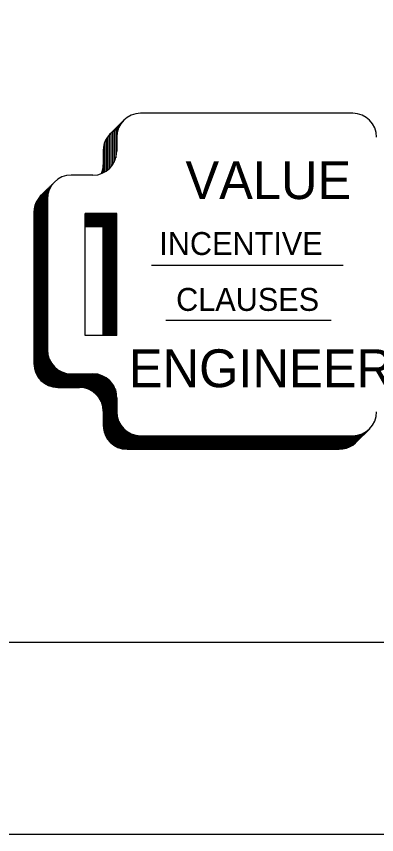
# Model space of a CAD drawing. Extents: x 22369.62 to 22373.29, y 22369.62 to 22372.46.
# Drawn here: x 22369.7905 to 22369.8691, y 22369.6213 to 22369.7998 of the extents above; entities that cross this region are included whole.
import ezdxf

# ---------------------------------------------------------------- set-up
doc = ezdxf.new("R2010")
doc.units = 0
for name, color, linetype in [('Level 1', 7, 'Continuous'), ('Level 2', 7, 'Continuous'), ('Level 7', 7, 'Continuous'), ('Level 9', 7, 'Continuous')]:
    doc.layers.add(name, color=color, linetype=linetype)

msp = doc.modelspace()

# ---------------------------------------------------------------- linework, layer by layer
at = {"layer": 'Level 1'}
msp.add_lwpolyline([(22369.6213, 22372.4553), (22373.288, 22372.4553), (22373.288, 22369.6213), (22369.6213, 22369.6213)], close=True, dxfattribs=at)
at = {"layer": 'Level 2'}
for p, q in [((22369.81094, 22369.77414), (22369.81388, 22369.77709)), ((22369.81261, 22369.775), (22369.81261, 22369.77582)), ((22369.81288, 22369.77568), (22369.81288, 22369.77609)), ((22369.81314, 22369.77614), (22369.81314, 22369.77635)), ((22369.81336, 22369.77648), (22369.81336, 22369.77657)), ((22369.81073, 22369.77391), (22369.81073, 22369.76654)), ((22369.81107, 22369.77428), (22369.81107, 22369.76689)), ((22369.81143, 22369.77463), (22369.81143, 22369.76735)), ((22369.8118, 22369.77501), (22369.8118, 22369.76798)), ((22369.81215, 22369.77536), (22369.81215, 22369.76887)), ((22369.81236, 22369.7734), (22369.81236, 22369.77557)), ((22369.8097, 22369.77214), (22369.8097, 22369.76579)), ((22369.81005, 22369.77295), (22369.81005, 22369.766)), ((22369.81037, 22369.77347), (22369.81037, 22369.76624)), ((22369.80941, 22369.77046), (22369.80941, 22369.76564)), ((22369.79581, 22369.76065), (22369.79876, 22369.7636)), ((22369.79661, 22369.76146), (22369.79661, 22369.71972)), ((22369.79676, 22369.7616), (22369.79676, 22369.71962)), ((22369.79689, 22369.76174), (22369.79689, 22369.71954)), ((22369.79703, 22369.76187), (22369.79703, 22369.71947)), ((22369.79712, 22369.76197), (22369.79712, 22369.71941)), ((22369.79724, 22369.75991), (22369.79724, 22369.76208)), ((22369.79735, 22369.761), (22369.79735, 22369.7622)), ((22369.7975, 22369.76154), (22369.7975, 22369.76234)), ((22369.79761, 22369.76185), (22369.79761, 22369.76246)), ((22369.79772, 22369.76209), (22369.79772, 22369.76256)), ((22369.79781, 22369.76229), (22369.79781, 22369.76265)), ((22369.79791, 22369.76249), (22369.79791, 22369.76276)), ((22369.79802, 22369.76265), (22369.79802, 22369.76286)), ((22369.79812, 22369.76282), (22369.79812, 22369.76297)), ((22369.79823, 22369.76297), (22369.79823, 22369.76307)), ((22369.79506, 22369.7597), (22369.79506, 22369.72132)), ((22369.79523, 22369.75995), (22369.79523, 22369.72107)), ((22369.7954, 22369.76019), (22369.7954, 22369.72083)), ((22369.79555, 22369.76036), (22369.79555, 22369.72065)), ((22369.79569, 22369.76052), (22369.79569, 22369.7205)), ((22369.79583, 22369.76066), (22369.79583, 22369.72035)), ((22369.79601, 22369.76085), (22369.79601, 22369.72019)), ((22369.79613, 22369.76098), (22369.79613, 22369.72007)), ((22369.79627, 22369.76111), (22369.79627, 22369.71997)), ((22369.79644, 22369.76128), (22369.79644, 22369.71984)), ((22369.79444, 22369.75819), (22369.79444, 22369.72283)), ((22369.79459, 22369.75872), (22369.79459, 22369.7223)), ((22369.79476, 22369.75912), (22369.79476, 22369.72189)), ((22369.79489, 22369.7594), (22369.79489, 22369.72161)), ((22369.79429, 22369.75697), (22369.79429, 22369.72405)), ((22369.81236, 22369.75665), (22369.80547, 22369.75665)), ((22369.81236, 22369.75652), (22369.80547, 22369.75652)), ((22369.81236, 22369.75636), (22369.80547, 22369.75636)), ((22369.81236, 22369.75621), (22369.80547, 22369.75621)), ((22369.81236, 22369.75604), (22369.80547, 22369.75604)), ((22369.81236, 22369.75679), (22369.80941, 22369.75384)), ((22369.81236, 22369.75588), (22369.80547, 22369.75588)), ((22369.81236, 22369.75573), (22369.80547, 22369.75573)), ((22369.81236, 22369.75556), (22369.80547, 22369.75556)), ((22369.81236, 22369.75541), (22369.80547, 22369.75541)), ((22369.81236, 22369.75526), (22369.80547, 22369.75526)), ((22369.81236, 22369.7551), (22369.80547, 22369.7551)), ((22369.81236, 22369.75496), (22369.80547, 22369.75496)), ((22369.81236, 22369.75481), (22369.80547, 22369.75481)), ((22369.81236, 22369.75469), (22369.80547, 22369.75469)), ((22369.81236, 22369.75453), (22369.80547, 22369.75453)), ((22369.81236, 22369.7544), (22369.80547, 22369.7544)), ((22369.81236, 22369.75427), (22369.80547, 22369.75427)), ((22369.81236, 22369.75414), (22369.80547, 22369.75414)), ((22369.81236, 22369.75399), (22369.80547, 22369.75399)), ((22369.80941, 22369.75384), (22369.80547, 22369.75384)), ((22369.80941, 22369.73012), (22369.80941, 22369.75384)), ((22369.80956, 22369.73012), (22369.80956, 22369.75399)), ((22369.80968, 22369.73012), (22369.80968, 22369.75399)), ((22369.8098, 22369.73012), (22369.8098, 22369.75399)), ((22369.8099, 22369.73012), (22369.8099, 22369.75399)), ((22369.81006, 22369.73012), (22369.81006, 22369.75399)), ((22369.8102, 22369.73012), (22369.8102, 22369.75399)), ((22369.81034, 22369.73012), (22369.81034, 22369.75399)), ((22369.81045, 22369.73012), (22369.81045, 22369.75399)), ((22369.81061, 22369.73012), (22369.81061, 22369.75399)), ((22369.81075, 22369.73012), (22369.81075, 22369.75399)), ((22369.81086, 22369.73012), (22369.81086, 22369.75399)), ((22369.811, 22369.73012), (22369.811, 22369.75399)), ((22369.81113, 22369.73012), (22369.81113, 22369.75399)), ((22369.81129, 22369.73012), (22369.81129, 22369.75399)), ((22369.81141, 22369.73012), (22369.81141, 22369.75399)), ((22369.81154, 22369.73012), (22369.81154, 22369.75399)), ((22369.8117, 22369.73012), (22369.8117, 22369.75399)), ((22369.81185, 22369.73012), (22369.81185, 22369.75399)), ((22369.81201, 22369.73012), (22369.81201, 22369.75399)), ((22369.81211, 22369.73012), (22369.81211, 22369.75399)), ((22369.81225, 22369.73012), (22369.81225, 22369.75399)), ((22369.79731, 22369.72613), (22369.79731, 22369.71932)), ((22369.79748, 22369.72544), (22369.79748, 22369.71925)), ((22369.79763, 22369.72501), (22369.79763, 22369.71919)), ((22369.79779, 22369.72466), (22369.79779, 22369.71913)), ((22369.79798, 22369.72432), (22369.79798, 22369.71907)), ((22369.79811, 22369.72411), (22369.79811, 22369.71903)), ((22369.79825, 22369.72391), (22369.79825, 22369.719)), ((22369.79843, 22369.72369), (22369.79843, 22369.71896)), ((22369.79857, 22369.72352), (22369.79857, 22369.71893)), ((22369.79873, 22369.72335), (22369.79873, 22369.7189)), ((22369.79888, 22369.7232), (22369.79888, 22369.71887)), ((22369.79904, 22369.72306), (22369.79904, 22369.71886)), ((22369.79919, 22369.72294), (22369.79919, 22369.71885)), ((22369.79936, 22369.7228), (22369.79936, 22369.71884)), ((22369.79952, 22369.72269), (22369.79952, 22369.71884)), ((22369.79968, 22369.72259), (22369.79968, 22369.71884)), ((22369.79983, 22369.7225), (22369.79983, 22369.71884)), ((22369.80002, 22369.72239), (22369.80002, 22369.71884)), ((22369.80015, 22369.72232), (22369.80015, 22369.71884)), ((22369.80024, 22369.72228), (22369.80024, 22369.71884)), ((22369.80037, 22369.72222), (22369.80037, 22369.71884)), ((22369.80051, 22369.72216), (22369.80051, 22369.71884)), ((22369.80068, 22369.7221), (22369.80068, 22369.71884)), ((22369.80084, 22369.72204), (22369.80084, 22369.71884)), ((22369.801, 22369.722), (22369.801, 22369.71884)), ((22369.80121, 22369.72194), (22369.80121, 22369.71884)), ((22369.80139, 22369.72189), (22369.80139, 22369.71884)), ((22369.80155, 22369.72186), (22369.80155, 22369.71884)), ((22369.80166, 22369.72185), (22369.80166, 22369.71884)), ((22369.80182, 22369.72183), (22369.80182, 22369.71884)), ((22369.80196, 22369.72181), (22369.80196, 22369.71884)), ((22369.80207, 22369.7218), (22369.80207, 22369.71884)), ((22369.80222, 22369.72179), (22369.80222, 22369.71884)), ((22369.80238, 22369.72179), (22369.80238, 22369.71884)), ((22369.80254, 22369.72179), (22369.80254, 22369.71884)), ((22369.80272, 22369.72179), (22369.80272, 22369.71884)), ((22369.80289, 22369.72179), (22369.80289, 22369.71884)), ((22369.80305, 22369.72179), (22369.80305, 22369.71884)), ((22369.80326, 22369.72179), (22369.80326, 22369.71884)), ((22369.80344, 22369.72179), (22369.80344, 22369.71884)), ((22369.80359, 22369.72179), (22369.80359, 22369.71884)), ((22369.80377, 22369.72179), (22369.80377, 22369.71884)), ((22369.80397, 22369.72179), (22369.80397, 22369.71884)), ((22369.80415, 22369.72179), (22369.80415, 22369.71884)), ((22369.80435, 22369.72179), (22369.80435, 22369.71884)), ((22369.80455, 22369.72179), (22369.80455, 22369.71884)), ((22369.80478, 22369.72179), (22369.80478, 22369.71881)), ((22369.80494, 22369.72179), (22369.80494, 22369.71879)), ((22369.80507, 22369.72179), (22369.80507, 22369.71877)), ((22369.80521, 22369.72179), (22369.80521, 22369.71875)), ((22369.80543, 22369.72179), (22369.80543, 22369.7187)), ((22369.80565, 22369.72179), (22369.80565, 22369.71863)), ((22369.80589, 22369.72179), (22369.80589, 22369.71856)), ((22369.80612, 22369.72179), (22369.80612, 22369.71848)), ((22369.80632, 22369.72179), (22369.80632, 22369.71839)), ((22369.80655, 22369.72179), (22369.80655, 22369.71829)), ((22369.80673, 22369.72179), (22369.80673, 22369.7182)), ((22369.807, 22369.72179), (22369.807, 22369.71803)), ((22369.80722, 22369.72179), (22369.80722, 22369.71788)), ((22369.80733, 22369.72179), (22369.80733, 22369.7178)), ((22369.80753, 22369.72179), (22369.80753, 22369.71764)), ((22369.80769, 22369.72176), (22369.80769, 22369.71751)), ((22369.80785, 22369.72174), (22369.80785, 22369.71735)), ((22369.80801, 22369.72172), (22369.80801, 22369.7172)), ((22369.80812, 22369.7217), (22369.80812, 22369.71707)), ((22369.8083, 22369.72166), (22369.8083, 22369.71685)), ((22369.80848, 22369.72162), (22369.80848, 22369.71661)), ((22369.80866, 22369.72157), (22369.80866, 22369.71632)), ((22369.80884, 22369.72151), (22369.80884, 22369.71601)), ((22369.809, 22369.72146), (22369.809, 22369.71568)), ((22369.80916, 22369.72138), (22369.80916, 22369.71523)), ((22369.80934, 22369.72131), (22369.80934, 22369.7145)), ((22369.80948, 22369.72125), (22369.80948, 22369.70976)), ((22369.80964, 22369.72115), (22369.80964, 22369.70903)), ((22369.80981, 22369.72106), (22369.80981, 22369.70857)), ((22369.80997, 22369.72097), (22369.80997, 22369.70823)), ((22369.81012, 22369.72086), (22369.81012, 22369.70794)), ((22369.81028, 22369.72075), (22369.81028, 22369.70769)), ((22369.81046, 22369.72061), (22369.81046, 22369.70744)), ((22369.81059, 22369.7205), (22369.81059, 22369.70726)), ((22369.81075, 22369.72035), (22369.81075, 22369.70708)), ((22369.7995, 22369.71884), (22369.80421, 22369.71884)), ((22369.81088, 22369.72022), (22369.81088, 22369.70694)), ((22369.81105, 22369.72004), (22369.81105, 22369.70677)), ((22369.81121, 22369.71985), (22369.81121, 22369.70663)), ((22369.81138, 22369.71962), (22369.81138, 22369.70648)), ((22369.81155, 22369.71937), (22369.81155, 22369.70635)), ((22369.81169, 22369.71915), (22369.81169, 22369.70626)), ((22369.81181, 22369.71891), (22369.81181, 22369.70618)), ((22369.81191, 22369.7187), (22369.81191, 22369.70611)), ((22369.81205, 22369.71836), (22369.81205, 22369.70603)), ((22369.81216, 22369.71801), (22369.81216, 22369.70597)), ((22369.81226, 22369.71761), (22369.81226, 22369.70591)), ((22369.80941, 22369.71363), (22369.80941, 22369.71056)), ((22369.81237, 22369.71318), (22369.81237, 22369.70586)), ((22369.81252, 22369.71224), (22369.81252, 22369.7058)), ((22369.81265, 22369.71179), (22369.81265, 22369.70574)), ((22369.81277, 22369.71149), (22369.81277, 22369.7057)), ((22369.81289, 22369.71122), (22369.81289, 22369.70564)), ((22369.813, 22369.71102), (22369.813, 22369.70561)), ((22369.81314, 22369.71077), (22369.81314, 22369.70557)), ((22369.81328, 22369.71056), (22369.81328, 22369.70553)), ((22369.81343, 22369.71035), (22369.81343, 22369.70549)), ((22369.81353, 22369.71023), (22369.81353, 22369.70547)), ((22369.81368, 22369.71005), (22369.81368, 22369.70544)), ((22369.81376, 22369.70996), (22369.81376, 22369.70543)), ((22369.81387, 22369.70984), (22369.81387, 22369.7054)), ((22369.814, 22369.70972), (22369.814, 22369.70539)), ((22369.81409, 22369.70963), (22369.81409, 22369.70538)), ((22369.8646, 22369.70687), (22369.86755, 22369.70982)), ((22369.81415, 22369.70958), (22369.81415, 22369.70537)), ((22369.81423, 22369.70952), (22369.81423, 22369.70536)), ((22369.81434, 22369.70943), (22369.81434, 22369.70536)), ((22369.81449, 22369.70931), (22369.81449, 22369.70536)), ((22369.81465, 22369.7092), (22369.81465, 22369.70536)), ((22369.8148, 22369.7091), (22369.8148, 22369.70536)), ((22369.81497, 22369.709), (22369.81497, 22369.70536)), ((22369.81512, 22369.70891), (22369.81512, 22369.70536)), ((22369.81528, 22369.70883), (22369.81528, 22369.70536)), ((22369.8154, 22369.70877), (22369.8154, 22369.70536)), ((22369.81555, 22369.70871), (22369.81555, 22369.70536)), ((22369.81572, 22369.70864), (22369.81572, 22369.70536)), ((22369.81588, 22369.70858), (22369.81588, 22369.70536)), ((22369.81605, 22369.70853), (22369.81605, 22369.70536)), ((22369.81623, 22369.70848), (22369.81623, 22369.70536)), ((22369.81641, 22369.70843), (22369.81641, 22369.70536)), ((22369.81656, 22369.70839), (22369.81656, 22369.70536)), ((22369.81675, 22369.70836), (22369.81675, 22369.70536)), ((22369.81691, 22369.70834), (22369.81691, 22369.70536)), ((22369.81708, 22369.70832), (22369.81708, 22369.70536)), ((22369.81728, 22369.70831), (22369.81728, 22369.70536)), ((22369.81745, 22369.7083), (22369.81745, 22369.70536)), ((22369.81745, 22369.70823), (22369.86091, 22369.70823)), ((22369.81745, 22369.70818), (22369.86091, 22369.70818)), ((22369.81745, 22369.70812), (22369.86091, 22369.70812)), ((22369.81745, 22369.70805), (22369.86091, 22369.70805)), ((22369.81745, 22369.70797), (22369.86091, 22369.70797)), ((22369.81745, 22369.70787), (22369.86091, 22369.70787)), ((22369.86091, 22369.70535), (22369.86091, 22369.7083)), ((22369.86103, 22369.70535), (22369.86103, 22369.7083)), ((22369.86111, 22369.70535), (22369.86111, 22369.7083)), ((22369.8612, 22369.70536), (22369.8612, 22369.7083)), ((22369.86133, 22369.70537), (22369.86133, 22369.7083)), ((22369.86144, 22369.70538), (22369.86144, 22369.7083)), ((22369.86156, 22369.70539), (22369.86156, 22369.7083)), ((22369.86166, 22369.7054), (22369.86166, 22369.7083)), ((22369.86178, 22369.70543), (22369.86178, 22369.7083)), ((22369.86187, 22369.70545), (22369.86187, 22369.7083)), ((22369.862, 22369.70547), (22369.862, 22369.7083)), ((22369.86211, 22369.70549), (22369.86211, 22369.7083)), ((22369.86223, 22369.70552), (22369.86223, 22369.7083)), ((22369.86237, 22369.70556), (22369.86237, 22369.7083)), ((22369.86253, 22369.70561), (22369.86253, 22369.7083)), ((22369.86265, 22369.70565), (22369.86265, 22369.7083)), ((22369.86278, 22369.7057), (22369.86278, 22369.7083)), ((22369.86291, 22369.70575), (22369.86291, 22369.7083)), ((22369.86305, 22369.70581), (22369.86305, 22369.7083)), ((22369.86316, 22369.70586), (22369.86316, 22369.7083)), ((22369.86332, 22369.70595), (22369.86332, 22369.7083)), ((22369.86348, 22369.70603), (22369.86348, 22369.7083)), ((22369.86362, 22369.70611), (22369.86362, 22369.7083)), ((22369.86377, 22369.70621), (22369.86377, 22369.7083)), ((22369.86391, 22369.7063), (22369.86391, 22369.7083)), ((22369.86405, 22369.7064), (22369.86405, 22369.7083)), ((22369.8642, 22369.70652), (22369.8642, 22369.7083)), ((22369.86435, 22369.70664), (22369.86435, 22369.70832)), ((22369.8645, 22369.70678), (22369.8645, 22369.70834)), ((22369.86462, 22369.70689), (22369.86462, 22369.70835)), ((22369.86476, 22369.70703), (22369.86476, 22369.70837)), ((22369.86486, 22369.70713), (22369.86486, 22369.70839)), ((22369.86499, 22369.70726), (22369.86499, 22369.70843)), ((22369.86509, 22369.70736), (22369.86509, 22369.70845)), ((22369.86521, 22369.70748), (22369.86521, 22369.70848)), ((22369.86533, 22369.7076), (22369.86533, 22369.70851)), ((22369.86541, 22369.70769), (22369.86541, 22369.70854)), ((22369.86552, 22369.70779), (22369.86552, 22369.70857)), ((22369.86561, 22369.70788), (22369.86561, 22369.7086)), ((22369.86572, 22369.70799), (22369.86572, 22369.70864)), ((22369.86578, 22369.70805), (22369.86578, 22369.70866)), ((22369.8659, 22369.70818), (22369.8659, 22369.70872)), ((22369.866, 22369.70827), (22369.866, 22369.70876)), ((22369.8661, 22369.70837), (22369.8661, 22369.70881)), ((22369.86622, 22369.70849), (22369.86622, 22369.70886)), ((22369.86631, 22369.70858), (22369.86631, 22369.70891)), ((22369.8664, 22369.70868), (22369.8664, 22369.70897)), ((22369.8665, 22369.70877), (22369.8665, 22369.70902)), ((22369.8666, 22369.70887), (22369.8666, 22369.70908)), ((22369.86671, 22369.70898), (22369.86671, 22369.70914)), ((22369.8668, 22369.70907), (22369.8668, 22369.70921)), ((22369.86689, 22369.70916), (22369.86689, 22369.70927)), ((22369.86699, 22369.70926), (22369.86699, 22369.70934)), ((22369.81745, 22369.70778), (22369.86091, 22369.70778)), ((22369.81745, 22369.7077), (22369.86091, 22369.7077)), ((22369.81745, 22369.7076), (22369.86091, 22369.7076)), ((22369.81745, 22369.70751), (22369.86091, 22369.70751)), ((22369.81745, 22369.70741), (22369.86091, 22369.70741)), ((22369.81745, 22369.70732), (22369.86091, 22369.70732)), ((22369.81745, 22369.70723), (22369.86091, 22369.70723)), ((22369.81745, 22369.70714), (22369.86091, 22369.70714)), ((22369.81745, 22369.70705), (22369.86091, 22369.70705)), ((22369.81745, 22369.70697), (22369.86091, 22369.70697)), ((22369.81745, 22369.70688), (22369.86091, 22369.70688)), ((22369.81745, 22369.70679), (22369.86091, 22369.70679)), ((22369.81745, 22369.7067), (22369.86091, 22369.7067)), ((22369.81745, 22369.70659), (22369.86091, 22369.70659)), ((22369.81745, 22369.70649), (22369.86091, 22369.70649)), ((22369.81745, 22369.70638), (22369.86091, 22369.70638)), ((22369.81745, 22369.70629), (22369.86091, 22369.70629)), ((22369.81745, 22369.70618), (22369.86091, 22369.70618)), ((22369.81745, 22369.70607), (22369.86091, 22369.70607)), ((22369.81462, 22369.70535), (22369.86091, 22369.70535)), ((22369.81745, 22369.70596), (22369.86091, 22369.70596)), ((22369.81745, 22369.70584), (22369.86091, 22369.70584)), ((22369.81745, 22369.70572), (22369.86091, 22369.70572)), ((22369.81745, 22369.7056), (22369.86091, 22369.7056)), ((22369.81745, 22369.70549), (22369.86091, 22369.70549))]:
    msp.add_line(p, q, dxfattribs=at)
for centre, start, end in [((22369.81462, 22369.77046), 111.4079, 180), ((22369.8042, 22369.76738), 338.5921, 0), ((22369.79949, 22369.75697), 111.4079, 180), ((22369.79949, 22369.72405), 180, 270), ((22369.8042, 22369.71363), 0, 90), ((22369.81462, 22369.71056), 180, 270), ((22369.86091, 22369.71056), 270, 338.5921)]:
    msp.add_arc(centre, 0.00521, start, end, dxfattribs=at)
at = {"layer": 'Level 7'}
for p, q in [((22369.86386, 22369.77861), (22369.81757, 22369.77861)), ((22369.81236, 22369.7734), (22369.81236, 22369.77033)), ((22369.80715, 22369.76512), (22369.80245, 22369.76512)), ((22369.79724, 22369.75991), (22369.79724, 22369.727)), ((22369.81236, 22369.75679), (22369.80547, 22369.75679)), ((22369.80547, 22369.73012), (22369.80547, 22369.75679)), ((22369.81236, 22369.73012), (22369.81236, 22369.75679)), ((22369.81991, 22369.74547), (22369.86174, 22369.74547)), ((22369.82306, 22369.73347), (22369.85915, 22369.73347)), ((22369.81236, 22369.73012), (22369.80547, 22369.73012)), ((22369.80245, 22369.72179), (22369.80715, 22369.72179)), ((22369.81236, 22369.71658), (22369.81236, 22369.71351)), ((22369.81757, 22369.7083), (22369.86386, 22369.7083))]:
    msp.add_line(p, q, dxfattribs=at)
for centre, start, end in [((22369.81756, 22369.77341), 90, 180), ((22369.86386, 22369.77341), 0, 90), ((22369.80715, 22369.77033), 270, 0), ((22369.80244, 22369.75992), 90, 180), ((22369.80244, 22369.727), 180, 270), ((22369.80715, 22369.71658), 0, 90), ((22369.81756, 22369.71351), 180, 270), ((22369.86386, 22369.71351), 270, 0)]:
    msp.add_arc(centre, 0.00521, start, end, dxfattribs=at)
at = {"layer": 'Level 9'}
msp.add_line((22369.7463, 22369.6633), (22373.017, 22369.6633), dxfattribs=at)

# ---------------------------------------------------------------- texts
at = {"layer": 'Level 2'}
for s, height, p in [('VALUE', 0.008249, (22369.82735, 22369.75991)), ('INCENTIVE', 0.005, (22369.82164, 22369.74771)), ('CLAUSES', 0.005, (22369.82531, 22369.73552)), ('ENGINEERING', 0.0082494, (22369.815, 22369.71888))]:
    msp.add_text(s, height=height, dxfattribs=at).set_placement(p)

doc.saveas('drawing.dxf')
